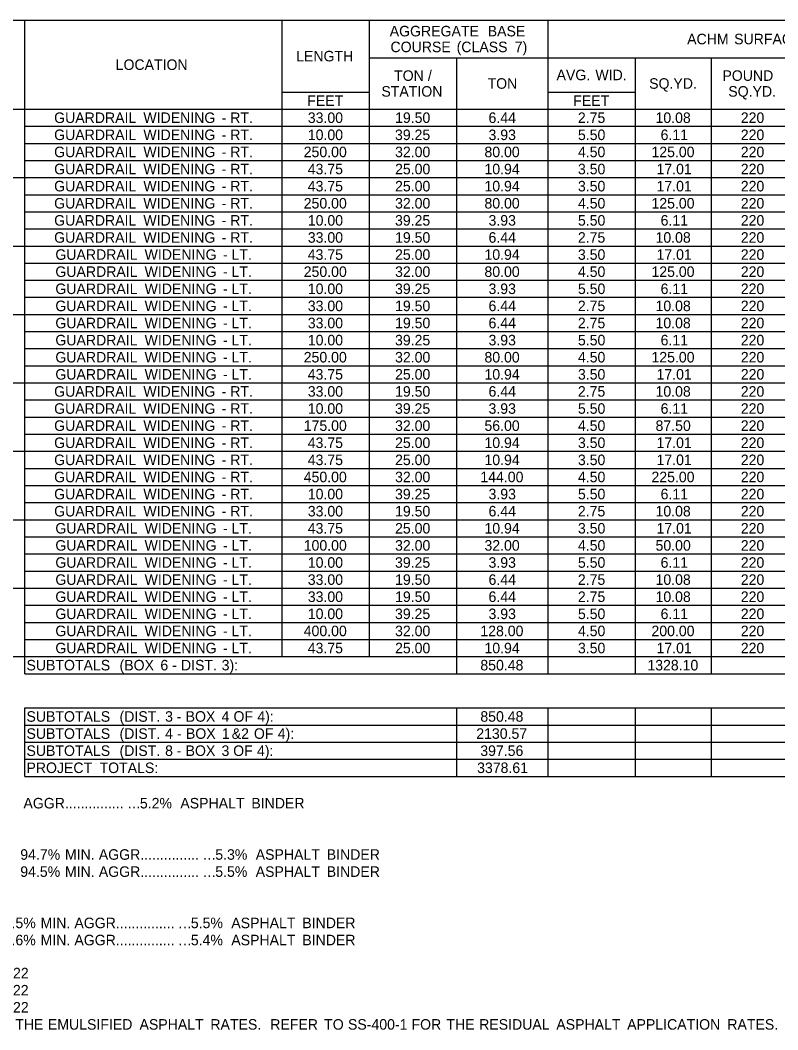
# Model space of a CAD drawing. Extents: x 540541 to 1930787, y -1948574 to 596640.
# Drawn here: x 559892 to 560324, y -1947042 to -1946466 of the extents above; entities that cross this region are included whole.
import ezdxf

# ---------------------------------------------------------------- set-up
doc = ezdxf.new("R2010")
doc.units = 0
doc.layers.add('Default', color=7, linetype='Continuous')

msp = doc.modelspace()

# ---------------------------------------------------------------- linework, layer by layer
at = {"layer": 'Default'}
for p, q in [((559673.34, -1946466.31), (560560.1, -1946466.31)), ((559894.67, -1946838.76), (559894.67, -1946466.31)), ((560041.4, -1946829.01), (560041.4, -1946466.31)), ((560091.13, -1946829.01), (560091.13, -1946466.31)), ((560193.02, -1946838.76), (560193.02, -1946466.31)), ((560091.13, -1946487.76), (560560.1, -1946487.76)), ((560140.85, -1946838.76), (560140.85, -1946487.76)), ((560242.74, -1946487.76), (560286.13, -1946487.76)), ((560242.74, -1946838.76), (560242.74, -1946487.76)), ((560286.13, -1946838.76), (560286.13, -1946487.76)), ((560041.4, -1946507.26), (560091.13, -1946507.26)), ((560091.13, -1946829.01), (560091.13, -1946507.26)), ((560193.02, -1946507.26), (560242.74, -1946507.26)), ((560193.02, -1946517.01), (560193.02, -1946507.26)), ((560242.74, -1946838.76), (560242.74, -1946507.26)), ((559673.34, -1946517.01), (560560.1, -1946517.01)), ((560041.4, -1946829.01), (560041.4, -1946517.01)), ((560091.13, -1946517.01), (560242.74, -1946517.01)), ((560140.85, -1946838.76), (560140.85, -1946517.01)), ((560242.74, -1946517.01), (560560.1, -1946517.01)), ((559894.67, -1946526.76), (560560.1, -1946526.76)), ((559894.67, -1946536.51), (560560.1, -1946536.51)), ((559894.67, -1946546.26), (560560.1, -1946546.26)), ((559844.94, -1946556.01), (560560.1, -1946556.01)), ((559894.67, -1946565.76), (560560.1, -1946565.76)), ((559894.67, -1946575.51), (560560.1, -1946575.51)), ((559894.67, -1946585.26), (560560.1, -1946585.26)), ((559844.94, -1946595.01), (560560.1, -1946595.01)), ((559894.67, -1946604.76), (560560.1, -1946604.76)), ((559894.67, -1946614.51), (560560.1, -1946614.51)), ((559894.67, -1946624.26), (560560.1, -1946624.26)), ((559844.94, -1946634.01), (560560.1, -1946634.01)), ((559894.67, -1946643.76), (560560.1, -1946643.76)), ((559894.67, -1946653.51), (560560.1, -1946653.51)), ((559894.67, -1946663.26), (560560.1, -1946663.26)), ((559673.34, -1946673.01), (560560.1, -1946673.01)), ((559894.67, -1946682.76), (560560.1, -1946682.76)), ((559894.67, -1946692.51), (560560.1, -1946692.51)), ((559894.67, -1946702.26), (560560.1, -1946702.26)), ((559844.94, -1946712.01), (560560.1, -1946712.01)), ((559894.67, -1946721.76), (560560.1, -1946721.76)), ((559894.67, -1946731.51), (560560.1, -1946731.51)), ((559894.67, -1946741.26), (560560.1, -1946741.26)), ((559844.94, -1946751.01), (560560.1, -1946751.01)), ((559894.67, -1946760.76), (560560.1, -1946760.76)), ((559894.67, -1946770.51), (560560.1, -1946770.51)), ((559894.67, -1946780.26), (560560.1, -1946780.26)), ((559844.94, -1946790.01), (560560.1, -1946790.01)), ((559894.67, -1946799.76), (560560.1, -1946799.76)), ((559894.67, -1946809.51), (560560.1, -1946809.51)), ((559894.67, -1946819.26), (560560.1, -1946819.26)), ((559673.34, -1946829.01), (560560.1, -1946829.01)), ((559894.67, -1946838.76), (559894.67, -1946829.01)), ((560193.02, -1946838.76), (560193.02, -1946829.01)), ((560286.13, -1946838.76), (560286.13, -1946829.01)), ((559894.67, -1946838.76), (560560.1, -1946838.76)), ((559894.67, -1946858.26), (560560.1, -1946858.26)), ((559894.67, -1946858.26), (560560.1, -1946858.26)), ((559894.67, -1946897.26), (559894.67, -1946858.26)), ((559894.67, -1946897.26), (559894.67, -1946858.26)), ((560140.85, -1946897.26), (560140.85, -1946858.26)), ((560193.02, -1946868.01), (560193.02, -1946858.26)), ((560193.02, -1946897.26), (560193.02, -1946858.26)), ((560242.74, -1946897.26), (560242.74, -1946858.26)), ((560242.74, -1946897.26), (560242.74, -1946858.26)), ((560286.13, -1946897.26), (560286.13, -1946858.26)), ((560286.13, -1946897.26), (560286.13, -1946858.26)), ((559894.67, -1946868.01), (560560.1, -1946868.01)), ((559894.67, -1946877.76), (560560.1, -1946877.76)), ((560193.02, -1946897.26), (560193.02, -1946877.76)), ((559894.67, -1946887.51), (560560.1, -1946887.51)), ((559894.67, -1946897.26), (560560.1, -1946897.26))]:
    msp.add_line(p, q, dxfattribs=at)

# ---------------------------------------------------------------- texts
for s, p in [('AGGREGATE', (560102.66, -1946475.54)), (' BASE', (560156.28, -1946475.54)), ('ACHM', (560272.16, -1946480.04)), (' SURFACE', (560296.71, -1946480.04)), ('COURSE', (560103.11, -1946484.54)), (' (CLASS', (560138.57, -1946484.54)), (' 7)', (560171.69, -1946484.54)), ('LENGTH', (560049.35, -1946489.79)), ('LOCATION', (559946.48, -1946494.66)), ('TON', (560105.15, -1946500.89)), (' /', (560122.17, -1946500.89)), ('AVG.', (560197.73, -1946500.51)), (' WID.', (560217.65, -1946500.51)), ('POUND', (560292.26, -1946500.89)), ('TON', (560158.42, -1946505.39)), ('SQ.YD.', (560250.51, -1946505.39)), ('STATION', (560097.93, -1946509.89)), ('SQ.YD.', (560295.61, -1946509.89)), ('FEET', (560055.64, -1946515.14)), ('FEET', (560207.25, -1946515.14)), ('GUARDRAIL', (559911.42, -1946524.89)), (' WIDENING', (559960.04, -1946524.89)), (' RT.', (560009.55, -1946524.89)), ('33.00', (560055.98, -1946524.89)), ('19.50', (560105.71, -1946524.89)), ('6.44', (560158.98, -1946524.89)), ('2.75', (560209.89, -1946524.89)), ('10.08', (560254.14, -1946524.89)), ('220', (560302.74, -1946524.89)), (' -', (560004.69, -1946524.89)), ('GUARDRAIL', (559911.42, -1946534.64)), (' WIDENING', (559960.04, -1946534.64)), (' -', (560004.69, -1946534.64)), (' RT.', (560009.55, -1946534.64)), ('10.00', (560055.98, -1946534.64)), ('39.25', (560105.67, -1946534.64)), ('3.93', (560158.97, -1946534.64)), ('5.50', (560209.93, -1946534.64)), ('6.11', (560257.05, -1946534.64)), ('220', (560302.74, -1946534.64)), ('GUARDRAIL', (559911.42, -1946544.39)), (' WIDENING', (559960.04, -1946544.39)), (' -', (560004.69, -1946544.39)), (' RT.', (560009.55, -1946544.39)), ('250.00', (560053.65, -1946544.39)), ('32.00', (560105.71, -1946544.39)), ('80.00', (560156.65, -1946544.39)), ('4.50', (560209.93, -1946544.39)), ('125.00', (560251.82, -1946544.39)), ('220', (560302.74, -1946544.39)), ('GUARDRAIL', (559911.42, -1946554.14)), (' WIDENING', (559960.04, -1946554.14)), (' RT.', (560009.55, -1946554.14)), ('43.75', (560055.95, -1946554.14)), ('25.00', (560105.71, -1946554.14)), ('10.94', (560156.65, -1946554.14)), ('3.50', (560209.93, -1946554.14)), ('17.01', (560254.72, -1946554.14)), ('220', (560302.74, -1946554.14)), (' -', (560004.69, -1946554.14)), ('GUARDRAIL', (559911.42, -1946563.89)), (' WIDENING', (559960.04, -1946563.89)), (' RT.', (560009.55, -1946563.89)), ('43.75', (560055.95, -1946563.89)), ('25.00', (560105.71, -1946563.89)), ('10.94', (560156.65, -1946563.89)), ('3.50', (560209.93, -1946563.89)), ('17.01', (560254.72, -1946563.89)), ('220', (560302.74, -1946563.89)), (' -', (560004.69, -1946563.89)), ('GUARDRAIL', (559911.42, -1946573.64)), (' WIDENING', (559960.04, -1946573.64)), (' -', (560004.69, -1946573.64)), (' RT.', (560009.55, -1946573.64)), ('250.00', (560053.65, -1946573.64)), ('32.00', (560105.71, -1946573.64)), ('80.00', (560156.65, -1946573.64)), ('4.50', (560209.93, -1946573.64)), ('125.00', (560251.82, -1946573.64)), ('220', (560302.74, -1946573.64)), ('GUARDRAIL', (559911.42, -1946583.39)), (' WIDENING', (559960.04, -1946583.39)), (' RT.', (560009.55, -1946583.39)), ('10.00', (560055.98, -1946583.39)), ('39.25', (560105.67, -1946583.39)), ('3.93', (560158.97, -1946583.39)), ('5.50', (560209.93, -1946583.39)), ('6.11', (560257.05, -1946583.39)), ('220', (560302.74, -1946583.39)), (' -', (560004.69, -1946583.39)), ('GUARDRAIL', (559911.42, -1946593.14)), (' WIDENING', (559960.04, -1946593.14)), (' RT.', (560009.55, -1946593.14)), ('33.00', (560055.98, -1946593.14)), ('19.50', (560105.71, -1946593.14)), ('6.44', (560158.98, -1946593.14)), ('2.75', (560209.89, -1946593.14)), ('10.08', (560254.14, -1946593.14)), ('220', (560302.74, -1946593.14)), (' -', (560004.69, -1946593.14)), ('GUARDRAIL', (559912.12, -1946602.89)), (' WIDENING', (559960.74, -1946602.89)), (' -', (560005.39, -1946602.89)), (' LT.', (560010.24, -1946602.89)), ('43.75', (560055.95, -1946602.89)), ('25.00', (560105.71, -1946602.89)), ('10.94', (560156.65, -1946602.89)), ('3.50', (560209.93, -1946602.89)), ('17.01', (560254.72, -1946602.89)), ('220', (560302.74, -1946602.89)), ('GUARDRAIL', (559912.12, -1946612.64)), (' WIDENING', (559960.74, -1946612.64)), (' LT.', (560010.24, -1946612.64)), ('250.00', (560053.65, -1946612.64)), ('32.00', (560105.71, -1946612.64)), ('80.00', (560156.65, -1946612.64)), ('4.50', (560209.93, -1946612.64)), ('125.00', (560251.82, -1946612.64)), ('220', (560302.74, -1946612.64)), (' -', (560005.39, -1946612.64)), ('GUARDRAIL', (559912.12, -1946622.39)), (' WIDENING', (559960.74, -1946622.39)), (' LT.', (560010.24, -1946622.39)), ('10.00', (560055.98, -1946622.39)), ('39.25', (560105.67, -1946622.39)), ('3.93', (560158.97, -1946622.39)), ('5.50', (560209.93, -1946622.39)), ('6.11', (560257.05, -1946622.39)), ('220', (560302.74, -1946622.39)), (' -', (560005.39, -1946622.39)), ('GUARDRAIL', (559912.12, -1946632.14)), (' WIDENING', (559960.74, -1946632.14)), (' -', (560005.39, -1946632.14)), (' LT.', (560010.24, -1946632.14)), ('33.00', (560055.98, -1946632.14)), ('19.50', (560105.71, -1946632.14)), ('6.44', (560158.98, -1946632.14)), ('2.75', (560209.89, -1946632.14)), ('10.08', (560254.14, -1946632.14)), ('220', (560302.74, -1946632.14)), ('GUARDRAIL', (559912.12, -1946641.89)), (' WIDENING', (559960.74, -1946641.89)), (' -', (560005.39, -1946641.89)), (' LT.', (560010.24, -1946641.89)), ('33.00', (560055.98, -1946641.89)), ('19.50', (560105.71, -1946641.89)), ('6.44', (560158.98, -1946641.89)), ('2.75', (560209.89, -1946641.89)), ('10.08', (560254.14, -1946641.89)), ('220', (560302.74, -1946641.89)), ('GUARDRAIL', (559912.12, -1946651.64)), (' WIDENING', (559960.74, -1946651.64)), (' LT.', (560010.24, -1946651.64)), ('10.00', (560055.98, -1946651.64)), ('39.25', (560105.67, -1946651.64)), ('3.93', (560158.97, -1946651.64)), ('5.50', (560209.93, -1946651.64)), ('6.11', (560257.05, -1946651.64)), ('220', (560302.74, -1946651.64)), (' -', (560005.39, -1946651.64)), ('GUARDRAIL', (559912.12, -1946661.39)), (' WIDENING', (559960.74, -1946661.39)), (' LT.', (560010.24, -1946661.39)), ('250.00', (560053.65, -1946661.39)), ('32.00', (560105.71, -1946661.39)), ('80.00', (560156.65, -1946661.39)), ('4.50', (560209.93, -1946661.39)), ('125.00', (560251.82, -1946661.39)), ('220', (560302.74, -1946661.39)), (' -', (560005.39, -1946661.39)), ('GUARDRAIL', (559912.12, -1946671.14)), (' WIDENING', (559960.74, -1946671.14)), (' -', (560005.39, -1946671.14)), (' LT.', (560010.24, -1946671.14)), ('43.75', (560055.95, -1946671.14)), ('25.00', (560105.71, -1946671.14)), ('10.94', (560156.65, -1946671.14)), ('3.50', (560209.93, -1946671.14)), ('17.01', (560254.72, -1946671.14)), ('220', (560302.74, -1946671.14)), ('GUARDRAIL', (559911.42, -1946680.89)), (' WIDENING', (559960.04, -1946680.89)), (' RT.', (560009.55, -1946680.89)), ('33.00', (560055.98, -1946680.89)), ('19.50', (560105.71, -1946680.89)), ('6.44', (560158.98, -1946680.89)), ('2.75', (560209.89, -1946680.89)), ('10.08', (560254.14, -1946680.89)), ('220', (560302.74, -1946680.89)), (' -', (560004.69, -1946680.89)), ('GUARDRAIL', (559911.42, -1946690.64)), (' WIDENING', (559960.04, -1946690.64)), (' RT.', (560009.55, -1946690.64)), ('10.00', (560055.98, -1946690.64)), ('39.25', (560105.67, -1946690.64)), ('3.93', (560158.97, -1946690.64)), ('5.50', (560209.93, -1946690.64)), ('6.11', (560257.05, -1946690.64)), ('220', (560302.74, -1946690.64)), (' -', (560004.69, -1946690.64)), ('GUARDRAIL', (559911.42, -1946700.39)), (' WIDENING', (559960.04, -1946700.39)), (' -', (560004.69, -1946700.39)), (' RT.', (560009.55, -1946700.39)), ('175.00', (560053.65, -1946700.39)), ('32.00', (560105.71, -1946700.39)), ('56.00', (560156.65, -1946700.39)), ('4.50', (560209.93, -1946700.39)), ('87.50', (560254.15, -1946700.39)), ('220', (560302.74, -1946700.39)), ('GUARDRAIL', (559911.42, -1946710.14)), (' WIDENING', (559960.04, -1946710.14)), (' RT.', (560009.55, -1946710.14)), ('43.75', (560055.95, -1946710.14)), ('25.00', (560105.71, -1946710.14)), ('10.94', (560156.65, -1946710.14)), ('3.50', (560209.93, -1946710.14)), ('17.01', (560254.72, -1946710.14)), ('220', (560302.74, -1946710.14)), (' -', (560004.69, -1946710.14)), ('GUARDRAIL', (559911.42, -1946719.89)), (' WIDENING', (559960.04, -1946719.89)), (' RT.', (560009.55, -1946719.89)), ('43.75', (560055.95, -1946719.89)), ('25.00', (560105.71, -1946719.89)), ('10.94', (560156.65, -1946719.89)), ('3.50', (560209.93, -1946719.89)), ('17.01', (560254.72, -1946719.89)), ('220', (560302.74, -1946719.89)), (' -', (560004.69, -1946719.89)), ('GUARDRAIL', (559911.42, -1946729.64)), (' WIDENING', (559960.04, -1946729.64)), (' -', (560004.69, -1946729.64)), (' RT.', (560009.55, -1946729.64)), ('450.00', (560053.65, -1946729.64)), ('32.00', (560105.71, -1946729.64)), ('144.00', (560154.32, -1946729.64)), ('4.50', (560209.93, -1946729.64)), ('225.00', (560251.82, -1946729.64)), ('220', (560302.74, -1946729.64)), ('GUARDRAIL', (559911.42, -1946739.39)), (' WIDENING', (559960.04, -1946739.39)), (' RT.', (560009.55, -1946739.39)), ('10.00', (560055.98, -1946739.39)), ('39.25', (560105.67, -1946739.39)), ('3.93', (560158.97, -1946739.39)), ('5.50', (560209.93, -1946739.39)), ('6.11', (560257.05, -1946739.39)), ('220', (560302.74, -1946739.39)), (' -', (560004.69, -1946739.39)), ('GUARDRAIL', (559911.42, -1946749.14)), (' WIDENING', (559960.04, -1946749.14)), (' RT.', (560009.55, -1946749.14)), ('33.00', (560055.98, -1946749.14)), ('19.50', (560105.71, -1946749.14)), ('6.44', (560158.98, -1946749.14)), ('2.75', (560209.89, -1946749.14)), ('10.08', (560254.14, -1946749.14)), ('220', (560302.74, -1946749.14)), (' -', (560004.69, -1946749.14)), ('GUARDRAIL', (559912.12, -1946758.89)), (' WIDENING', (559960.74, -1946758.89)), (' -', (560005.39, -1946758.89)), (' LT.', (560010.24, -1946758.89)), ('43.75', (560055.95, -1946758.89)), ('25.00', (560105.71, -1946758.89)), ('10.94', (560156.65, -1946758.89)), ('3.50', (560209.93, -1946758.89)), ('17.01', (560254.72, -1946758.89)), ('220', (560302.74, -1946758.89)), ('GUARDRAIL', (559912.12, -1946768.64)), (' WIDENING', (559960.74, -1946768.64)), (' -', (560005.39, -1946768.64)), (' LT.', (560010.24, -1946768.64)), ('100.00', (560053.65, -1946768.64)), ('32.00', (560105.71, -1946768.64)), ('32.00', (560156.65, -1946768.64)), ('4.50', (560209.93, -1946768.64)), ('50.00', (560254.15, -1946768.64)), ('220', (560302.74, -1946768.64)), ('GUARDRAIL', (559912.12, -1946778.39)), (' WIDENING', (559960.74, -1946778.39)), (' LT.', (560010.24, -1946778.39)), ('10.00', (560055.98, -1946778.39)), ('39.25', (560105.67, -1946778.39)), ('3.93', (560158.97, -1946778.39)), ('5.50', (560209.93, -1946778.39)), ('6.11', (560257.05, -1946778.39)), ('220', (560302.74, -1946778.39)), (' -', (560005.39, -1946778.39)), ('GUARDRAIL', (559912.12, -1946788.14)), (' WIDENING', (559960.74, -1946788.14)), (' LT.', (560010.24, -1946788.14)), ('33.00', (560055.98, -1946788.14)), ('19.50', (560105.71, -1946788.14)), ('6.44', (560158.98, -1946788.14)), ('2.75', (560209.89, -1946788.14)), ('10.08', (560254.14, -1946788.14)), ('220', (560302.74, -1946788.14)), (' -', (560005.39, -1946788.14)), ('GUARDRAIL', (559912.12, -1946797.89)), (' WIDENING', (559960.74, -1946797.89)), (' -', (560005.39, -1946797.89)), (' LT.', (560010.24, -1946797.89)), ('33.00', (560055.98, -1946797.89)), ('19.50', (560105.71, -1946797.89)), ('6.44', (560158.98, -1946797.89)), ('2.75', (560209.89, -1946797.89)), ('10.08', (560254.14, -1946797.89)), ('220', (560302.74, -1946797.89)), ('GUARDRAIL', (559912.12, -1946807.64)), (' WIDENING', (559960.74, -1946807.64)), (' LT.', (560010.24, -1946807.64)), ('10.00', (560055.98, -1946807.64)), ('39.25', (560105.67, -1946807.64)), ('3.93', (560158.97, -1946807.64)), ('5.50', (560209.93, -1946807.64)), ('6.11', (560257.05, -1946807.64)), ('220', (560302.74, -1946807.64)), (' -', (560005.39, -1946807.64)), ('GUARDRAIL', (559912.12, -1946817.39)), (' WIDENING', (559960.74, -1946817.39)), (' LT.', (560010.24, -1946817.39)), ('400.00', (560053.65, -1946817.39)), ('32.00', (560105.71, -1946817.39)), ('128.00', (560154.32, -1946817.39)), ('4.50', (560209.93, -1946817.39)), ('200.00', (560251.82, -1946817.39)), ('220', (560302.74, -1946817.39)), (' -', (560005.39, -1946817.39)), ('GUARDRAIL', (559912.12, -1946827.14)), (' WIDENING', (559960.74, -1946827.14)), (' -', (560005.39, -1946827.14)), (' LT.', (560010.24, -1946827.14)), ('43.75', (560055.95, -1946827.14)), ('25.00', (560105.71, -1946827.14)), ('10.94', (560156.65, -1946827.14)), ('3.50', (560209.93, -1946827.14)), ('17.01', (560254.72, -1946827.14)), ('220', (560302.74, -1946827.14)), ('SUBTOTALS', (559895.64, -1946836.89)), (' (BOX', (559946.47, -1946836.89)), (' 6', (559969.74, -1946836.89)), (' DIST.', (559981.49, -1946836.89)), (' 3):', (560004.67, -1946836.89)), ('850.48', (560154.31, -1946836.89)), ('1328.10', (560249.5, -1946836.89)), (' -', (559976.44, -1946836.89)), (' (DIST.', (559946.47, -1946866.14)), (' 4):', (560024.98, -1946866.14)), ('SUBTOTALS', (559895.64, -1946866.14)), (' 3', (559972.43, -1946866.14)), (' -', (559979.06, -1946866.14)), (' BOX', (559984.12, -1946866.14)), (' 4', (560004.61, -1946866.14)), (' OF', (560011.4, -1946866.14)), ('850.48', (560154.31, -1946866.14)), ('SUBTOTALS', (559895.64, -1946875.89)), (' (DIST.', (559946.47, -1946875.89)), (' 4', (559972.43, -1946875.89)), (' BOX', (559984.29, -1946875.89)), (' 1', (560004.78, -1946875.89)), (' &2', (560010.4, -1946875.89)), (' OF', (560023.03, -1946875.89)), (' 4):', (560036.61, -1946875.89)), ('2130.57', (560151.98, -1946875.89)), (' -', (559979.23, -1946875.89)), ('SUBTOTALS', (559895.64, -1946885.64)), (' (DIST.', (559946.47, -1946885.64)), (' 8', (559972.43, -1946885.64)), (' -', (559979.05, -1946885.64)), (' BOX', (559984.1, -1946885.64)), (' 3', (560004.59, -1946885.64)), (' OF', (560011.22, -1946885.64)), (' 4):', (560024.8, -1946885.64)), ('397.56', (560154.27, -1946885.64)), ('PROJECT', (559895.64, -1946895.39)), (' TOTALS:', (559935.07, -1946895.39)), ('3378.61', (560152.47, -1946895.39)), (' AGGR...............', (559891.7, -1946915.56)), ('5.2%', (559960.3, -1946915.56)), ('  ASPHALT', (559978.88, -1946915.56)), (' BINDER', (560021.58, -1946915.56)), ('…', (559952.9, -1946915.56)), ('94.7%', (559892.12, -1946944.81)), (' MIN.', (559915.36, -1946944.81)), (' AGGR...............', (559934.65, -1946944.81)), ('5.3%', (560003.25, -1946944.81)), ('  ASPHALT', (560021.83, -1946944.81)), (' BINDER', (560064.53, -1946944.81)), ('…', (559995.85, -1946944.81)), ('94.5%', (559892.12, -1946954.56)), (' MIN.', (559915.36, -1946954.56)), (' AGGR...............', (559934.65, -1946954.56)), ('5.5%', (560003.25, -1946954.56)), ('  ASPHALT', (560021.83, -1946954.56)), (' BINDER', (560064.53, -1946954.56)), ('…', (559995.85, -1946954.56)), ('94.5%', (559878.2, -1946983.81)), (' MIN.', (559901.44, -1946983.81)), (' AGGR...............', (559920.73, -1946983.81)), ('5.5%', (559989.33, -1946983.81)), ('  ASPHALT', (560007.92, -1946983.81)), (' BINDER', (560050.61, -1946983.81)), ('…', (559981.94, -1946983.81)), ('94.6%', (559878.2, -1946993.56)), (' MIN.', (559901.44, -1946993.56)), (' AGGR...............', (559920.73, -1946993.56)), ('5.4%', (559989.33, -1946993.56)), ('  ASPHALT', (560007.92, -1946993.56)), (' BINDER', (560050.61, -1946993.56)), ('…', (559981.94, -1946993.56)), (' 64-22', (559874.16, -1947012.39)), (' 70-22', (559874.1, -1947022.14)), (' 76-22', (559874.16, -1947031.89)), (' THE', (559887.01, -1947041.64)), (' EMULSIFIED', (559905.66, -1947041.64)), (' ASPHALT', (559957.85, -1947041.64)), (' RATES.', (559998.22, -1947041.64)), ('  REFER', (560030.1, -1947041.64)), (' TO', (560063.06, -1947041.64)), (' SS-400-1', (560076.65, -1947041.64)), (' FOR', (560112.85, -1947041.64)), (' THE', (560132.76, -1947041.64)), (' RESIDUAL', (560151.41, -1947041.64)), (' ASPHALT', (560195.37, -1947041.64)), (' APPLICATION', (560235.74, -1947041.64)), (' RATES.', (560292.82, -1947041.64))]:
    msp.add_text(s, height=6, dxfattribs=at).set_placement(p)

doc.saveas('drawing.dxf')
